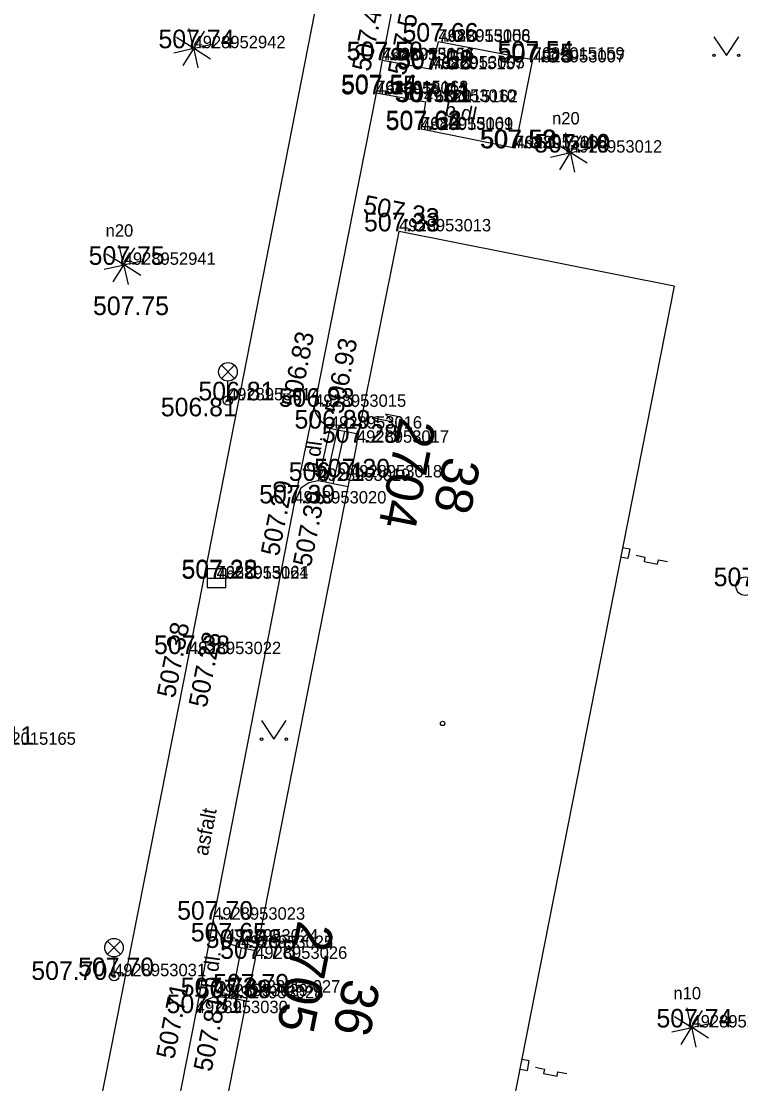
# Model space of a CAD drawing. Extents: x -669251 to -668549, y -1128351 to -1127698.
# Drawn here: x -668739.91 to -668710.85, y -1128134.75 to -1128091.87 of the extents above; entities that cross this region are included whole.
import ezdxf

# ---------------------------------------------------------------- set-up
doc = ezdxf.new("R2010")
doc.units = 0
for name, color, linetype in [('Vrstva 1', 7, 'Continuous'), ('Vrstva 10', 7, 'Continuous'), ('Vrstva 11', 7, 'Continuous'), ('Vrstva 2', 7, 'Continuous'), ('Vrstva 22', 7, 'Continuous'), ('Vrstva 24', 7, 'Continuous'), ('Vrstva 27', 7, 'Continuous'), ('Vrstva 3', 7, 'Continuous'), ('Vrstva 33', 7, 'Continuous'), ('Vrstva 36', 7, 'Continuous'), ('Vrstva 40', 7, 'Continuous'), ('Vrstva 43', 7, 'Continuous'), ('Vrstva 44', 7, 'Continuous'), ('Vrstva 47', 7, 'Continuous'), ('Vrstva 5', 7, 'Continuous'), ('Vrstva 58', 7, 'Continuous'), ('Vrstva 6', 7, 'Continuous')]:
    doc.layers.add(name, color=color, linetype=linetype)

msp = doc.modelspace()

# ---------------------------------------------------------------- linework, layer by layer
at = {"layer": 'Vrstva 1'}
for p, q in [((-668732.95, -1128092.96), (-668732.95, -1128092.96)), ((-668723.06, -1128092.69), (-668723.06, -1128092.69)), ((-668723.06, -1128092.7), (-668723.06, -1128092.7)), ((-668725.34, -1128093.45), (-668725.34, -1128093.45)), ((-668725.33, -1128093.44), (-668725.33, -1128093.44)), ((-668719.26, -1128093.42), (-668719.26, -1128093.42)), ((-668723.32, -1128093.81), (-668723.32, -1128093.81)), ((-668723.29, -1128093.77), (-668723.29, -1128093.77)), ((-668719.24, -1128093.53), (-668719.24, -1128093.53)), ((-668725.57, -1128094.77), (-668725.57, -1128094.77)), ((-668725.58, -1128094.82), (-668725.58, -1128094.82)), ((-668723.64, -1128095.12), (-668723.64, -1128095.12)), ((-668723.57, -1128095.14), (-668723.57, -1128095.14)), ((-668723.76, -1128096.23), (-668723.76, -1128096.23)), ((-668723.76, -1128096.26), (-668723.76, -1128096.26)), ((-668719.97, -1128096.99), (-668719.97, -1128096.99)), ((-668719.94, -1128097), (-668719.94, -1128097)), ((-668717.74, -1128097.17), (-668717.74, -1128097.17)), ((-668724.65, -1128100.35), (-668724.65, -1128100.35)), ((-668735.77, -1128101.7), (-668735.77, -1128101.7)), ((-668731.56, -1128107.17), (-668731.56, -1128107.17)), ((-668728.08, -1128107.43), (-668728.08, -1128107.43)), ((-668727.44, -1128108.31), (-668727.44, -1128108.31)), ((-668726.35, -1128108.88), (-668726.35, -1128108.88)), ((-668727.91, -1128110.42), (-668727.91, -1128110.42)), ((-668726.63, -1128110.28), (-668726.63, -1128110.28)), ((-668728.88, -1128111.33), (-668728.88, -1128111.33)), ((-668732.02, -1128114.35), (-668732.02, -1128114.35)), ((-668732.02, -1128114.37), (-668732.02, -1128114.37)), ((-668733.13, -1128117.41), (-668733.13, -1128117.41)), ((-668732.16, -1128128.13), (-668732.16, -1128128.13)), ((-668731.63, -1128129.01), (-668731.63, -1128129.01)), ((-668731.03, -1128129.27), (-668731.03, -1128129.27)), ((-668730.46, -1128129.71), (-668730.46, -1128129.71)), ((-668736.16, -1128130.41), (-668736.16, -1128130.41)), ((-668730.74, -1128131.07), (-668730.74, -1128131.07)), ((-668732.05, -1128131.22), (-668732.05, -1128131.22)), ((-668731.42, -1128131.3), (-668731.42, -1128131.3)), ((-668732.86, -1128131.9), (-668732.86, -1128131.9)), ((-668712.84, -1128132.48), (-668712.84, -1128132.48))]:
    msp.add_line(p, q, dxfattribs=at)
at = {"layer": 'Vrstva 10'}
for p, q in [((-668724.22, -1128087.61), (-668725.33, -1128093.44)), ((-668733.13, -1128117.41), (-668727.49, -1128088.64)), ((-668723.32, -1128093.81), (-668723.06, -1128092.69)), ((-668723.06, -1128092.69), (-668719.26, -1128093.42)), ((-668725.33, -1128093.44), (-668725.57, -1128094.77)), ((-668725.33, -1128093.44), (-668723.32, -1128093.81)), ((-668719.26, -1128093.42), (-668719.97, -1128096.99)), ((-668725.57, -1128094.77), (-668728.08, -1128107.43)), ((-668723.57, -1128095.14), (-668725.57, -1128094.77)), ((-668723.76, -1128096.23), (-668723.57, -1128095.14)), ((-668719.97, -1128096.99), (-668723.76, -1128096.23)), ((-668728.88, -1128111.33), (-668728.08, -1128107.43)), ((-668728.88, -1128111.33), (-668732.16, -1128128.13)), ((-668738.83, -1128146.21), (-668733.13, -1128117.41)), ((-668732.16, -1128128.13), (-668732.86, -1128131.9)), ((-668732.05, -1128131.22), (-668731.42, -1128131.3)), ((-668732.86, -1128131.9), (-668735.82, -1128146.96))]:
    msp.add_line(p, q, dxfattribs=at)
for points in [[(-668727.44, -1128108.31), (-668727.787, -1128108.042), (-668728.016, -1128107.667), (-668728.08, -1128107.43)], [(-668727.91, -1128110.42), (-668728.294, -1128110.497), (-668728.615, -1128110.72), (-668728.88, -1128111.33)], [(-668731.03, -1128129.27), (-668731.472, -1128129.114), (-668731.836, -1128128.819), (-668732.08, -1128128.419), (-668732.16, -1128128.13)], [(-668732.05, -1128131.22), (-668732.435, -1128131.374), (-668732.86, -1128131.9)]]:
    msp.add_lwpolyline(points, dxfattribs=at)
at = {"layer": 'Vrstva 11'}
for p, q in [((-668727.44, -1128108.31), (-668727.91, -1128110.42)), ((-668727.146, -1128108.369), (-668727.615, -1128110.478)), ((-668727.146, -1128108.369), (-668727.44, -1128108.31)), ((-668726.851, -1128108.428), (-668727.321, -1128110.536)), ((-668726.851, -1128108.428), (-668727.146, -1128108.369)), ((-668726.282, -1128108.541), (-668726.851, -1128108.428)), ((-668727.615, -1128110.478), (-668727.91, -1128110.42)), ((-668727.321, -1128110.536), (-668727.615, -1128110.478)), ((-668726.704, -1128110.658), (-668727.321, -1128110.536)), ((-668731.03, -1128129.27), (-668731.42, -1128131.3)), ((-668730.398, -1128129.395), (-668731.03, -1128129.27)), ((-668730.81, -1128131.421), (-668731.42, -1128131.3))]:
    msp.add_line(p, q, dxfattribs=at)
at = {"layer": 'Vrstva 22'}
for p, q in [((-668732.958, -1128092.92), (-668733.13, -1128092.166)), ((-668732.984, -1128092.94), (-668733.64, -1128092.526)), ((-668732.516, -1128092.27), (-668732.93, -1128092.926)), ((-668733.744, -1128093.14), (-668732.99, -1128092.968)), ((-668732.97, -1128092.994), (-668733.384, -1128093.65)), ((-668732.942, -1128093), (-668732.77, -1128093.754)), ((-668732.26, -1128093.394), (-668732.916, -1128092.98)), ((-668732.91, -1128092.952), (-668732.156, -1128092.78)), ((-668717.748, -1128097.13), (-668717.92, -1128096.376)), ((-668717.306, -1128096.48), (-668717.72, -1128097.136)), ((-668717.774, -1128097.15), (-668718.43, -1128096.736)), ((-668718.534, -1128097.35), (-668717.78, -1128097.178)), ((-668717.76, -1128097.204), (-668718.174, -1128097.86)), ((-668717.732, -1128097.21), (-668717.56, -1128097.964)), ((-668717.05, -1128097.604), (-668717.706, -1128097.19)), ((-668717.7, -1128097.162), (-668716.946, -1128096.99)), ((-668735.778, -1128101.66), (-668735.95, -1128100.906)), ((-668735.336, -1128101.01), (-668735.75, -1128101.666)), ((-668735.804, -1128101.68), (-668736.46, -1128101.266)), ((-668735.73, -1128101.692), (-668734.976, -1128101.52)), ((-668736.564, -1128101.88), (-668735.81, -1128101.708)), ((-668735.79, -1128101.734), (-668736.204, -1128102.39)), ((-668735.762, -1128101.74), (-668735.59, -1128102.494)), ((-668735.08, -1128102.134), (-668735.736, -1128101.72)), ((-668712.874, -1128132.46), (-668713.53, -1128132.046)), ((-668712.848, -1128132.44), (-668713.02, -1128131.686)), ((-668712.406, -1128131.79), (-668712.82, -1128132.446)), ((-668713.634, -1128132.66), (-668712.88, -1128132.488)), ((-668712.15, -1128132.914), (-668712.806, -1128132.5)), ((-668712.8, -1128132.472), (-668712.046, -1128132.3)), ((-668712.86, -1128132.514), (-668713.274, -1128133.17)), ((-668712.832, -1128132.52), (-668712.66, -1128133.274))]:
    msp.add_line(p, q, dxfattribs=at)
for centre in [(-668732.95, -1128092.96), (-668717.74, -1128097.17), (-668735.77, -1128101.7), (-668712.84, -1128132.48)]:
    msp.add_circle(centre, 0.04, dxfattribs=at)
at = {"layer": 'Vrstva 24'}
for p, q in [((-668725.899, -1128107.644), (-668726.095, -1128107.605)), ((-668726.174, -1128107.997), (-668725.977, -1128108.036)), ((-668725.977, -1128108.036), (-668725.899, -1128107.644)), ((-668725.48, -1128107.819), (-668725.742, -1128107.879)), ((-668724.884, -1128108.05), (-668725.742, -1128107.879)), ((-668725.742, -1128107.879), (-668725.523, -1128108.035)), ((-668724.589, -1128107.854), (-668725.203, -1128107.732)), ((-668725.203, -1128107.732), (-668724.884, -1128108.05)), ((-668715.629, -1128113.108), (-668715.335, -1128113.166)), ((-668715.335, -1128113.166), (-668715.413, -1128113.558)), ((-668715.413, -1128113.558), (-668715.707, -1128113.5)), ((-668730.031, -1128128.571), (-668730.227, -1128128.532)), ((-668730.147, -1128129.16), (-668730.031, -1128128.571)), ((-668729.631, -1128128.843), (-668729.893, -1128128.904)), ((-668729.035, -1128129.073), (-668729.893, -1128128.904)), ((-668729.893, -1128128.904), (-668729.674, -1128129.059)), ((-668728.74, -1128128.876), (-668729.354, -1128128.755)), ((-668729.354, -1128128.755), (-668729.035, -1128129.073)), ((-668730.343, -1128129.121), (-668730.147, -1128129.16)), ((-668719.389, -1128133.826), (-668719.683, -1128133.766)), ((-668719.763, -1128134.158), (-668719.469, -1128134.218)), ((-668719.469, -1128134.218), (-668719.389, -1128133.826))]:
    msp.add_line(p, q, dxfattribs=at)
for points in [[(-668715.08, -1128113.421), (-668714.719, -1128113.493), (-668714.755, -1128113.673), (-668714.213, -1128113.78), (-668714.177, -1128113.601), (-668713.815, -1128113.671)], [(-668719.135, -1128134.082), (-668718.775, -1128134.156), (-668718.811, -1128134.336), (-668718.27, -1128134.446), (-668718.233, -1128134.267), (-668717.872, -1128134.339)]]:
    msp.add_lwpolyline(points, dxfattribs=at)
at = {"layer": 'Vrstva 27'}
msp.add_line((-668732.395, -1128114.35), (-668731.645, -1128114.35), dxfattribs=at)
msp.add_lwpolyline([(-668732.395, -1128114.724), (-668731.645, -1128114.724), (-668731.645, -1128113.974), (-668732.395, -1128113.974)], close=True, dxfattribs=at)
msp.add_circle((-668710.67, -1128114.67), 0.375, dxfattribs=at)
at = {"layer": 'Vrstva 33'}
for p, q in [((-668731.825, -1128105.755), (-668731.295, -1128106.285)), ((-668731.825, -1128106.285), (-668731.295, -1128105.755)), ((-668731.56, -1128107.17), (-668731.56, -1128106.395)), ((-668736.425, -1128128.995), (-668735.895, -1128129.525)), ((-668736.425, -1128129.525), (-668735.895, -1128128.995)), ((-668736.16, -1128130.41), (-668736.16, -1128129.635))]:
    msp.add_line(p, q, dxfattribs=at)
for centre, radius in [((-668731.56, -1128106.02), 0.375), ((-668731.56, -1128107.17), 0.19), ((-668731.56, -1128107.17), 0.05), ((-668736.16, -1128129.26), 0.375), ((-668736.16, -1128130.41), 0.19), ((-668736.16, -1128130.41), 0.05)]:
    msp.add_circle(centre, radius, dxfattribs=at)
at = {"layer": 'Vrstva 36'}
for p, q in [((-668711.932, -1128092.499), (-668711.432, -1128093.249)), ((-668711.432, -1128093.249), (-668710.932, -1128092.499)), ((-668730.202, -1128120.093), (-668729.702, -1128120.843)), ((-668729.702, -1128120.843), (-668729.202, -1128120.093))]:
    msp.add_line(p, q, dxfattribs=at)
for centre in [(-668711.932, -1128093.249), (-668710.932, -1128093.249), (-668730.202, -1128120.843), (-668729.202, -1128120.843)]:
    msp.add_circle(centre, 0.05, dxfattribs=at)
at = {"layer": 'Vrstva 5'}
for p, q in [((-668726.282, -1128108.541), (-668724.65, -1128100.35)), ((-668713.538, -1128102.563), (-668724.65, -1128100.35)), ((-668713.538, -1128102.563), (-668720.332, -1128136.951)), ((-668726.35, -1128108.88), (-668726.282, -1128108.541)), ((-668726.704, -1128110.658), (-668726.63, -1128110.28)), ((-668730.398, -1128129.395), (-668726.704, -1128110.658)), ((-668730.46, -1128129.71), (-668730.398, -1128129.395)), ((-668730.81, -1128131.421), (-668730.74, -1128131.07)), ((-668732.43, -1128139.59), (-668730.81, -1128131.421))]:
    msp.add_line(p, q, dxfattribs=at)
at = {"layer": 'Vrstva 58'}
msp.add_circle((-668722.889, -1128120.211), 0.0875, dxfattribs=at)
at = {"layer": 'Vrstva 6'}
for p, q in [((-668726.35, -1128108.88), (-668726.63, -1128110.28)), ((-668730.46, -1128129.71), (-668730.74, -1128131.07))]:
    msp.add_line(p, q, dxfattribs=at)

# ---------------------------------------------------------------- texts
at = {"layer": 'Vrstva 2'}
for s, p in [('4928953006', (-668723.06, -1128092.7)), ('7682015158', (-668723.06, -1128092.69)), ('4928952942', (-668732.95, -1128092.96)), ('4928953004', (-668725.34, -1128093.45)), ('7682015156', (-668725.33, -1128093.44)), ('7682015159', (-668719.26, -1128093.42)), ('4928953007', (-668719.24, -1128093.53)), ('7682015157', (-668723.32, -1128093.81)), ('4928953005', (-668723.29, -1128093.77)), ('4928953011', (-668725.58, -1128094.82)), ('7682015163', (-668725.57, -1128094.77)), ('4928953010', (-668723.64, -1128095.12)), ('7682015162', (-668723.57, -1128095.14)), ('4928953009', (-668723.76, -1128096.26)), ('7682015161', (-668723.76, -1128096.23)), ('7682015160', (-668719.97, -1128096.99)), ('4928953008', (-668719.94, -1128097)), ('4928953012', (-668717.74, -1128097.17)), ('4928953013', (-668724.65, -1128100.35)), ('4928952941', (-668735.77, -1128101.7)), ('4928953014', (-668731.56, -1128107.17)), ('4928953015', (-668728.08, -1128107.43)), ('4928953016', (-668727.44, -1128108.31)), ('4928953017', (-668726.35, -1128108.88)), ('4928953018', (-668726.63, -1128110.28)), ('4928953019', (-668727.91, -1128110.42)), ('4928953020', (-668728.88, -1128111.33)), ('4928953021', (-668732.02, -1128114.37)), ('7682015164', (-668732.02, -1128114.35)), ('4928953022', (-668733.13, -1128117.41)), ('7682015165', (-668741.42, -1128121.07)), ('4928953023', (-668732.16, -1128128.13)), ('4928953024', (-668731.63, -1128129.01)), ('4928953025', (-668731.03, -1128129.27)), ('4928953026', (-668730.46, -1128129.71)), ('4928953031', (-668736.16, -1128130.41)), ('4928953029', (-668732.05, -1128131.22)), ('4928953027', (-668730.74, -1128131.07)), ('4928953028', (-668731.42, -1128131.3)), ('4928953030', (-668732.86, -1128131.9)), ('4928952921', (-668712.84, -1128132.48))]:
    msp.add_text(s, height=0.5, dxfattribs=at).set_placement(p)
at = {"layer": 'Vrstva 3'}
for s, rotation, p in [('507.48 ', 78.7288, (-668725.827, -1128093.933)), ('507.58 ', 78.7288, (-668724.382, -1128094.087)), ('507.33 ', 348.7367, (-668726.142, -1128099.608)), ('506.83 ', 78.7806, (-668728.668, -1128107.488)), ('506.93 ', 78.7806, (-668726.926, -1128107.75)), ('507.29 ', 78.7806, (-668729.51, -1128113.491)), ('507.39 ', 78.7806, (-668728.214, -1128113.923)), ('507.38 ', 78.7162, (-668733.709, -1128119.217)), ('507.28 ', 78.7162, (-668732.425, -1128119.604)), ('507.71 ', 78.7806, (-668733.735, -1128133.79)), ('507.81 ', 78.7806, (-668732.225, -1128134.297))]:
    msp.add_text(s, height=0.75, rotation=rotation, dxfattribs=at).set_placement(p)
for s, p in [('507.66 ', (-668724.512, -1128092.69)), ('507.66 ', (-668724.512, -1128092.7)), ('507.74 ', (-668734.365, -1128092.96)), ('507.56 ', (-668726.768, -1128093.44)), ('507.58 ', (-668726.755, -1128093.45)), ('507.58 ', (-668724.735, -1128093.81)), ('507.69 ', (-668724.722, -1128093.77)), ('507.54 ', (-668720.675, -1128093.42)), ('507.55 ', (-668720.655, -1128093.53)), ('507.55 ', (-668726.995, -1128094.82)), ('507.54 ', (-668726.985, -1128094.77)), ('507.61 ', (-668724.832, -1128095.12)), ('507.61 ', (-668724.762, -1128095.14)), ('507.62 ', (-668725.189, -1128096.23)), ('507.64 ', (-668725.189, -1128096.26)), ('507.52 ', (-668721.385, -1128096.99)), ('507.53 ', (-668721.355, -1128097)), ('507.40 ', (-668719.191, -1128097.17)), ('507.33 ', (-668726.065, -1128100.35)), ('507.75 ', (-668737.185, -1128101.7)), ('507.75 ', (-668737.009, -1128103.728)), ('506.81 ', (-668732.752, -1128107.17)), ('506.93 ', (-668729.511, -1128107.43)), ('506.81 ', (-668734.271, -1128107.814)), ('506.89 ', (-668728.872, -1128108.31)), ('507.28 ', (-668727.765, -1128108.88)), ('506.91 ', (-668729.104, -1128110.42)), ('507.30 ', (-668728.081, -1128110.28)), ('507.39 ', (-668730.298, -1128111.33)), ('507.22 ', (-668733.435, -1128114.35)), ('507.25 ', (-668733.435, -1128114.37)), ('507.15 ', (-668711.944, -1128114.67)), ('507.38 ', (-668734.545, -1128117.41)), ('508.11 ', (-668742.457, -1128121.07)), ('507.70 ', (-668733.611, -1128128.13)), ('507.65 ', (-668733.059, -1128129.01)), ('507.68 ', (-668732.459, -1128129.27)), ('507.78 ', (-668731.875, -1128129.71)), ('507.70 ', (-668739.5, -1128130.56)), ('507.70 ', (-668737.611, -1128130.41)), ('507.79 ', (-668732.158, -1128131.07)), ('507.73 ', (-668733.465, -1128131.22)), ('507.69 ', (-668732.852, -1128131.3)), ('507.81 ', (-668734.038, -1128131.9)), ('507.74 ', (-668714.255, -1128132.48))]:
    msp.add_text(s, height=0.75, dxfattribs=at).set_placement(p)
at = {"layer": 'Vrstva 40'}
for s, rotation, p in [('b.dl.', 348.661, (-668722.85, -1128095.699)), ('b.dl.', 82.3494, (-668727.93, -1128110.137)), ('asfalt', 78.9527, (-668732.376, -1128125.58)), ('b.dl.', 82.3494, (-668732.046, -1128130.925))]:
    msp.add_text(s, height=0.6, rotation=rotation, dxfattribs=at).set_placement(p)
at = {"layer": 'Vrstva 43'}
for s, p in [('2704', (-668724.616, -1128107.804)), ('2705', (-668728.73, -1128128.123))]:
    msp.add_text(s, height=1.5, rotation=258.8472, dxfattribs=at).set_placement(p)
at = {"layer": 'Vrstva 44'}
for s, rotation, p in [('38', 258.6901, (-668722.821, -1128109.384)), ('36', 258.3664, (-668726.87, -1128130.454))]:
    msp.add_text(s, height=1.5, rotation=rotation, dxfattribs=at).set_placement(p)
at = {"layer": 'Vrstva 47'}
for s, p in [('n20', (-668718.47, -1128096.034)), ('n20', (-668736.5, -1128100.564)), ('n10', (-668713.57, -1128131.344))]:
    msp.add_text(s, height=0.5, dxfattribs=at).set_placement(p)

doc.saveas('drawing.dxf')
